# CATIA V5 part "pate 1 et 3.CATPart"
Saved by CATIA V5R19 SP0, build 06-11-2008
Part number: Part1
Bounding box of the stored display mesh (mm): x -10 to 10, y -132.951 to 10, z -9.996 to 52.236
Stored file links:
  D:\thinkmotion-MPB\Dropbox\CIAO82010_JCF\BAUVIN\554_bauvin\pate 1 et 3.CATPart
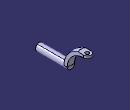
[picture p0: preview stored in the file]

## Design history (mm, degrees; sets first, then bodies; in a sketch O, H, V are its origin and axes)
Body1 (main body)
  Sketch1 on yz-plane, origin (0, 0, 0), H (0, 1, 0), V (0, 0, 1)
    arc A1 centre (0, 0) radius 55 from (0, 55) to (-55, 0) ccw
    point P1 (-55, 0)
    point P2 (0, 55)
    line L1 (0, 55) -> (0, 0)
    line L2 (0, 0) -> (-55, 0)
    radius A1 = 55
    coincidence: P1 H, P2 V
    vertical: L1 V
    horizontal: L2 H
  Shaft1: profile Sketch1, axis Sketch1.H, angle 90, second angle 90
  Sketch2 on yz-plane, origin (0, 0, 0), H (0, 1, 0), V (0, 0, 1)
    point P1 (0, 0)
    line L1 (0, 0) -> (-132.951, 0)
    line L2 (-132.951, 0) -> (-132.951, 10)
    line L3 (-132.951, 10) -> (0, 10)
    line L4 (0, 10) -> (0, 0)
    reference projected line E1 (0, 53.3762) -> (0, 0) from edge [face of Shaft1 from Sketch1.A1 | face of Shaft1 from Sketch1.L1]
    length L2 = 10
    coincidence: P1 H, L4 E1
    horizontal: L1 H, L3 H
    vertical: L2 V, L4 V
  Shaft2: profile Sketch2, axis Sketch2.H, angle 0, second angle 360
  Sketch3 on zx-plane, origin (0, 0, 0), H (-1, 0, 0), V (0, 0, 1)
    line L1 (10, 72.1496) -> (90, 72.1496)
    line L2 (90, 72.1496) -> (90, -19.84)
    line L3 (90, -19.84) -> (10, -19.84)
    line L4 (10, -19.84) -> (10, 72.1496)
    line L5 (-90, 72.1496) -> (-10, 72.1496)
    line L6 (-10, -19.84) -> (-90, -19.84)
    line L7 (-10, 72.1496) -> (-10, -19.84)
    line L8 (-90, -19.84) -> (-90, 72.1496)
    length L1 = 80
    length L5 = 80
    distance L7 L4 = 20
    horizontal: L1 H, L3 H, L5 H, L6 H
    vertical: L2 V, L4 V, L7 V, L8 V
    symmetry: L4 L7 V
    coincidence: L1 L5, L3 L6
    parallelism: L2 L8
  Pocket1: profile Sketch3, direction (0, -1, 0), through (limit type 3)
  Sketch4 on face of Pocket1 from Sketch3.L7, origin (10, 0, 0), H (0, 1, 0), V (0, 0, 1)
    arc A1 centre (0, 0) radius 45 from (0, 45) to (-45, 0) ccw
    point P1 (-45, 0)
    point P2 (0, 45)
    line L1 (0, 45) -> (0, -39.8895)
    line L2 (0, -39.8895) -> (-45, -39.8895)
    line L3 (-45, -39.8895) -> (-45, 0)
    radius A1 = 45
    coincidence: P1 H, P2 V
    vertical: L1 V
    horizontal: L2 H
    tangency: L3 A1
  Pocket2: profile Sketch4, direction (1, 0, 0), through (limit type 3)
  Plane1: type Angle, RefPlane face of Shaft2, Direction edge [face of Pocket2 from Sketch4.A1 | face of Shaft2], Angle 90
  Sketch5 on Plane1, origin (0, 0, 45), H (1, 0, 0), V (0, 1, 0)
    arc A1 centre (0, 0) radius 10 from (10, 0) to (-10, 0) ccw
    point P1 (-10, 0)
    point P2 (10, 0)
    line L1 (10, 0) -> (-10, 0)
    reference projected point E1 (-10, 0) from vertex [face of Shaft2 | face of Pocket2 from Sketch4.A1 | face of Pocket1 from Sketch3.L4]
    coincidence: P1 H, P2 H, P1 E1
    horizontal: L1 H
  Pad1: profile Sketch5, direction (0, 0, 1), length 6.8
  Sketch6 on yz-plane, origin (0, 0, 0), H (0, 1, 0), V (0, 0, 1)
    line L1 (-17.1874, 59.8134) -> (21.7787, 59.8134)
    line L2 (21.7787, 59.8134) -> (21.7787, 51.8)
    line L3 (21.7787, 51.8) -> (-17.1874, 51.8)
    line L4 (-17.1874, 51.8) -> (-17.1874, 59.8134)
    reference projected line E1 (0, 51.8) -> (10, 51.8) from edge [face of Pad1 from Sketch5.A1 | end face of Pad1]
    horizontal: L1 H, L3 H
    vertical: L2 V, L4 V
    coincidence: L3 E1
  Pocket3: profile Sketch6, direction (-1, 0, 0), length 20, mirrored extent
  Sketch7 on face of Pocket3, origin (0, 0, 51.8), H (1, 0, 0), V (0, 1, 0)
    circle A1 centre (0, 0) radius 5
    radius A1 = 5
  Pocket4: profile Sketch7, direction (0, 0, -1), through (limit type 3)
  Point1: type Center, Curve edge [face of Pocket2 from Sketch4.L3 | face of Shaft2 from Sketch2.L3]
  Line1: type Normal, RefPoint Point1, RefSkin face of Pocket2 from Sketch4.L3, Start 0, End 20
  Plane2: type Offset, RefPlane zx-plane, Offset 60, reversed
  Point2: type Center, Curve edge [face of Pocket3 | face of Pocket4 from Sketch7.A1]
  Line2: type Normal, RefPoint Point2, RefSkin face of Pocket3, Start 0, End 20
  Plane3: type 2Lines, Element1 Line1, Element2 Line2
  Point3: type OnPlane, Support Plane3, H 0, V 0, Direction (0, 1, 0)
  Line3: type Normal, RefPoint Point3, RefSkin Plane3, Start 0, End 20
